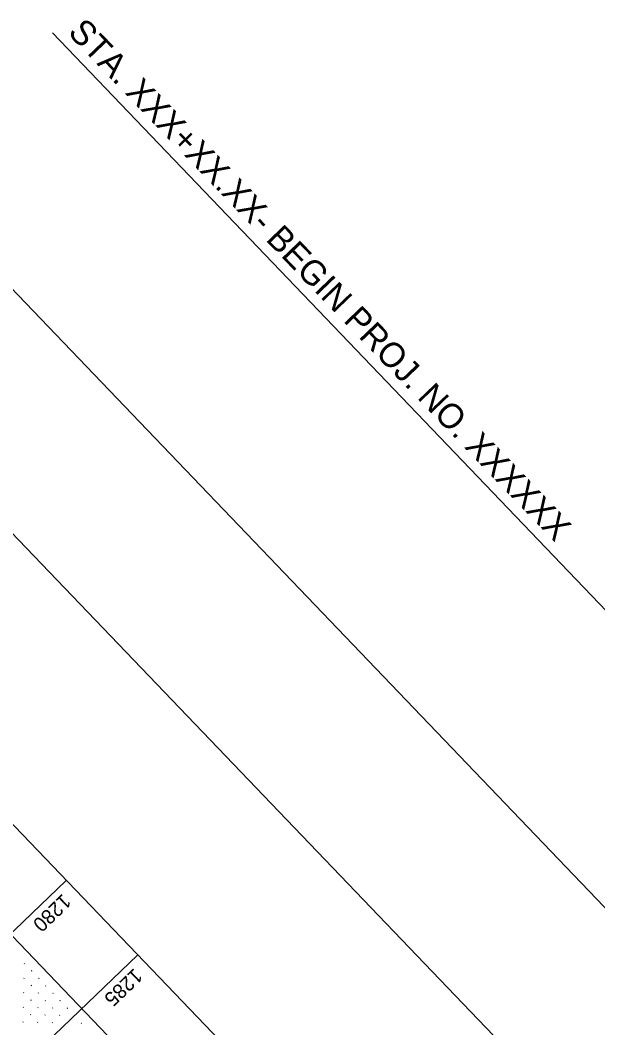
# Model space of a CAD drawing. Extents: x 2148987 to 2151117, y 142806 to 144993.
# Drawn here: x 2150343.4 to 2150623.4, y 144504.6 to 144993 of the extents above; entities that cross this region are included whole.
import ezdxf

# ---------------------------------------------------------------- set-up
doc = ezdxf.new("R2010")
doc.units = 0
for name, color, linetype in [('2', 7, 'Continuous'), ('BASELINE', 7, 'Continuous'), ('PR_ABUT_PH3', 7, 'Continuous'), ('PR_PIER_PH3', 7, 'Continuous'), ('PR_Road_Concrete', 7, 'Continuous'), ('SHT_Profile_Grid_Minor', 7, 'Continuous'), ('SHT_Standard_Sheet_Txt', 7, 'Continuous'), ('Wall D Bore', 7, 'Continuous')]:
    doc.layers.add(name, color=color, linetype=linetype)

msp = doc.modelspace()

# ---------------------------------------------------------------- linework, layer by layer
at = {"layer": '2'}
msp.add_lwpolyline([(2150359.02, 144986.77), (2150704.97, 144625.77), (2150852.58, 144582.84), (2150889.19, 144433.54)], dxfattribs=at)
at = {"layer": 'BASELINE'}
msp.add_lwpolyline([(2151029.45, 144024.32), (2149802.07, 142848.08), (2149040.98, 143642.27), (2150268.36, 144818.51)], close=True, dxfattribs=at)
at = {"layer": 'PR_ABUT_PH3'}
msp.add_lwpolyline([(2151117.11, 144051.19), (2149817.52, 142805.76), (2148987.24, 143672.15), (2150286.82, 144917.58)], close=True, dxfattribs=at)
at = {"layer": 'PR_PIER_PH3'}
for p, q in [((2150365.75, 144575.97), (2149228.62, 143486.22)), ((2150400.35, 144539.87), (2149263.21, 143450.12))]:
    msp.add_line(p, q, dxfattribs=at)
at = {"layer": 'PR_Road_Concrete'}
msp.add_line((2150200.3, 144694.42), (2150546.25, 144333.42), dxfattribs=at)
msp.add_lwpolyline([(2150941.76, 143974.91), (2149804.63, 142885.16), (2149078.13, 143643.25), (2150215.26, 144733)], close=True, dxfattribs=at)
at = {"layer": 'SHT_Profile_Grid_Minor'}
for p, q in [((2150345.54, 144535.82), (2150345.36, 144535.64)), ((2150349, 144532.21), (2150348.82, 144532.03)), ((2150345.39, 144528.75), (2150345.21, 144528.57)), ((2150352.46, 144528.6), (2150352.28, 144528.42)), ((2150345.24, 144521.68), (2150345.06, 144521.5)), ((2150348.85, 144525.14), (2150348.67, 144524.96)), ((2150352.31, 144521.53), (2150352.12, 144521.35)), ((2150355.92, 144524.99), (2150355.73, 144524.81)), ((2150359.37, 144521.38), (2150359.19, 144521.2)), ((2150348.7, 144518.07), (2150348.51, 144517.89)), ((2150355.76, 144517.92), (2150355.58, 144517.74)), ((2150362.83, 144517.77), (2150362.65, 144517.59)), ((2150345.09, 144514.61), (2150344.9, 144514.44)), ((2150348.54, 144511), (2150348.36, 144510.83)), ((2150352.15, 144514.46), (2150351.97, 144514.28)), ((2150355.61, 144510.85), (2150355.43, 144510.67)), ((2150359.22, 144514.31), (2150359.04, 144514.13)), ((2150362.68, 144510.7), (2150362.5, 144510.52)), ((2150366.29, 144514.16), (2150366.11, 144513.98)), ((2150344.93, 144507.54), (2150344.75, 144507.37)), ((2150352, 144507.39), (2150351.82, 144507.22)), ((2150359.07, 144507.24), (2150358.89, 144507.06)), ((2150373.21, 144506.94), (2150373.03, 144506.76))]:
    msp.add_line(p, q, dxfattribs=at)

# ---------------------------------------------------------------- texts
at = {"layer": 'SHT_Standard_Sheet_Txt'}
msp.add_text('STA. XXX+XX.XX- BEGIN PROJ. NO. XXXXXX', height=12, rotation=313.7809, dxfattribs=at).set_placement((2150366.09, 144986.62))
at = {"layer": 'Wall D Bore'}
for s, p in [('1280', (2150364.04, 144569.95)), ('1285', (2150398.64, 144533.85))]:
    msp.add_text(s, height=7, rotation=223.7809, dxfattribs=at).set_placement(p)

doc.saveas('drawing.dxf')
